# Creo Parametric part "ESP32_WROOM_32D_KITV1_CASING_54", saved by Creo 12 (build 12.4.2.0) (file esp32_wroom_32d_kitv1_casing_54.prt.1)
Units: Custom; MM, KILOGRAM, SECS

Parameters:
  PTC_WM_ITERATION = "0"
  PTC_WM_VERSION = "-.0"
  PTC_WM_LIFECYCLE_STATE = "In Work"
  PTC_WM_LIFECYCLE = "MO_CADDocument"
  PTC_WM_CREATED_BY = "Maximilian Roepper (Z0017RMS: MO)"
  PTC_WM_CREATED_ON = "18-Sep-26 11:36:42 AM"
  PTC_WM_MODIFIED_BY = "Maximilian Roepper (Z0017RMS: MO)"
  PTC_WM_MODIFIED_ON = "18-Sep-26 11:36:46 AM"
  PDMLINKNUMBER = "PDM000071455247"
  PTC_WM_NAME = "esp32_wroom_32d_kitv1_casing_54.prt"
  PTC_WM_NUMBER = "PDM000071455247"

Other parameters: WEIGHT, WEIGHT_FACTOR, WEIGHT_ADD, _MASS_TEMP, _DIFF_TEMP, MC_ERRORS, SUPPLIER

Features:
  1. coordinate system
  2. datum plane "PRT_YZ"
  3. datum plane "PRT_XY"
  4. datum plane "PRT_XZ"
  5. coordinate system
  6. datum axis
  7. datum axis
  8. datum axis
  9. coordinate system
  10. imported feature
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
Other named items: PRT, SIEMENS_MO, DRW_VIEW_ORG, PRT_X, PRT_Y, PRT_Z, CS0, ROUGH_GROB

Layers: 00_STD_CSYS-KSYS, 01_STD_PLANES-EBENEN, 02_STD_AXES-ACHSEN, 03_STD_CSYS-KSYS, 24_IMPORT_FEAT-IMPORT_KE

Surfaces: 5 plane, 1 cylinder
